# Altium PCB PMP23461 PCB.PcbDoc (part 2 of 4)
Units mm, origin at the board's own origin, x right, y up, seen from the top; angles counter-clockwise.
Board outline 240.04 x 159.92 mm, 6 copper layers (Layer 1, Layer 2, Layer 3, Layer 4, Layer 5, Layer 6), stack 2.017 mm thick; 241 components, 120 nets, 654 pads, 744 vias.
Unrouted connection lines stored in the file: 3.
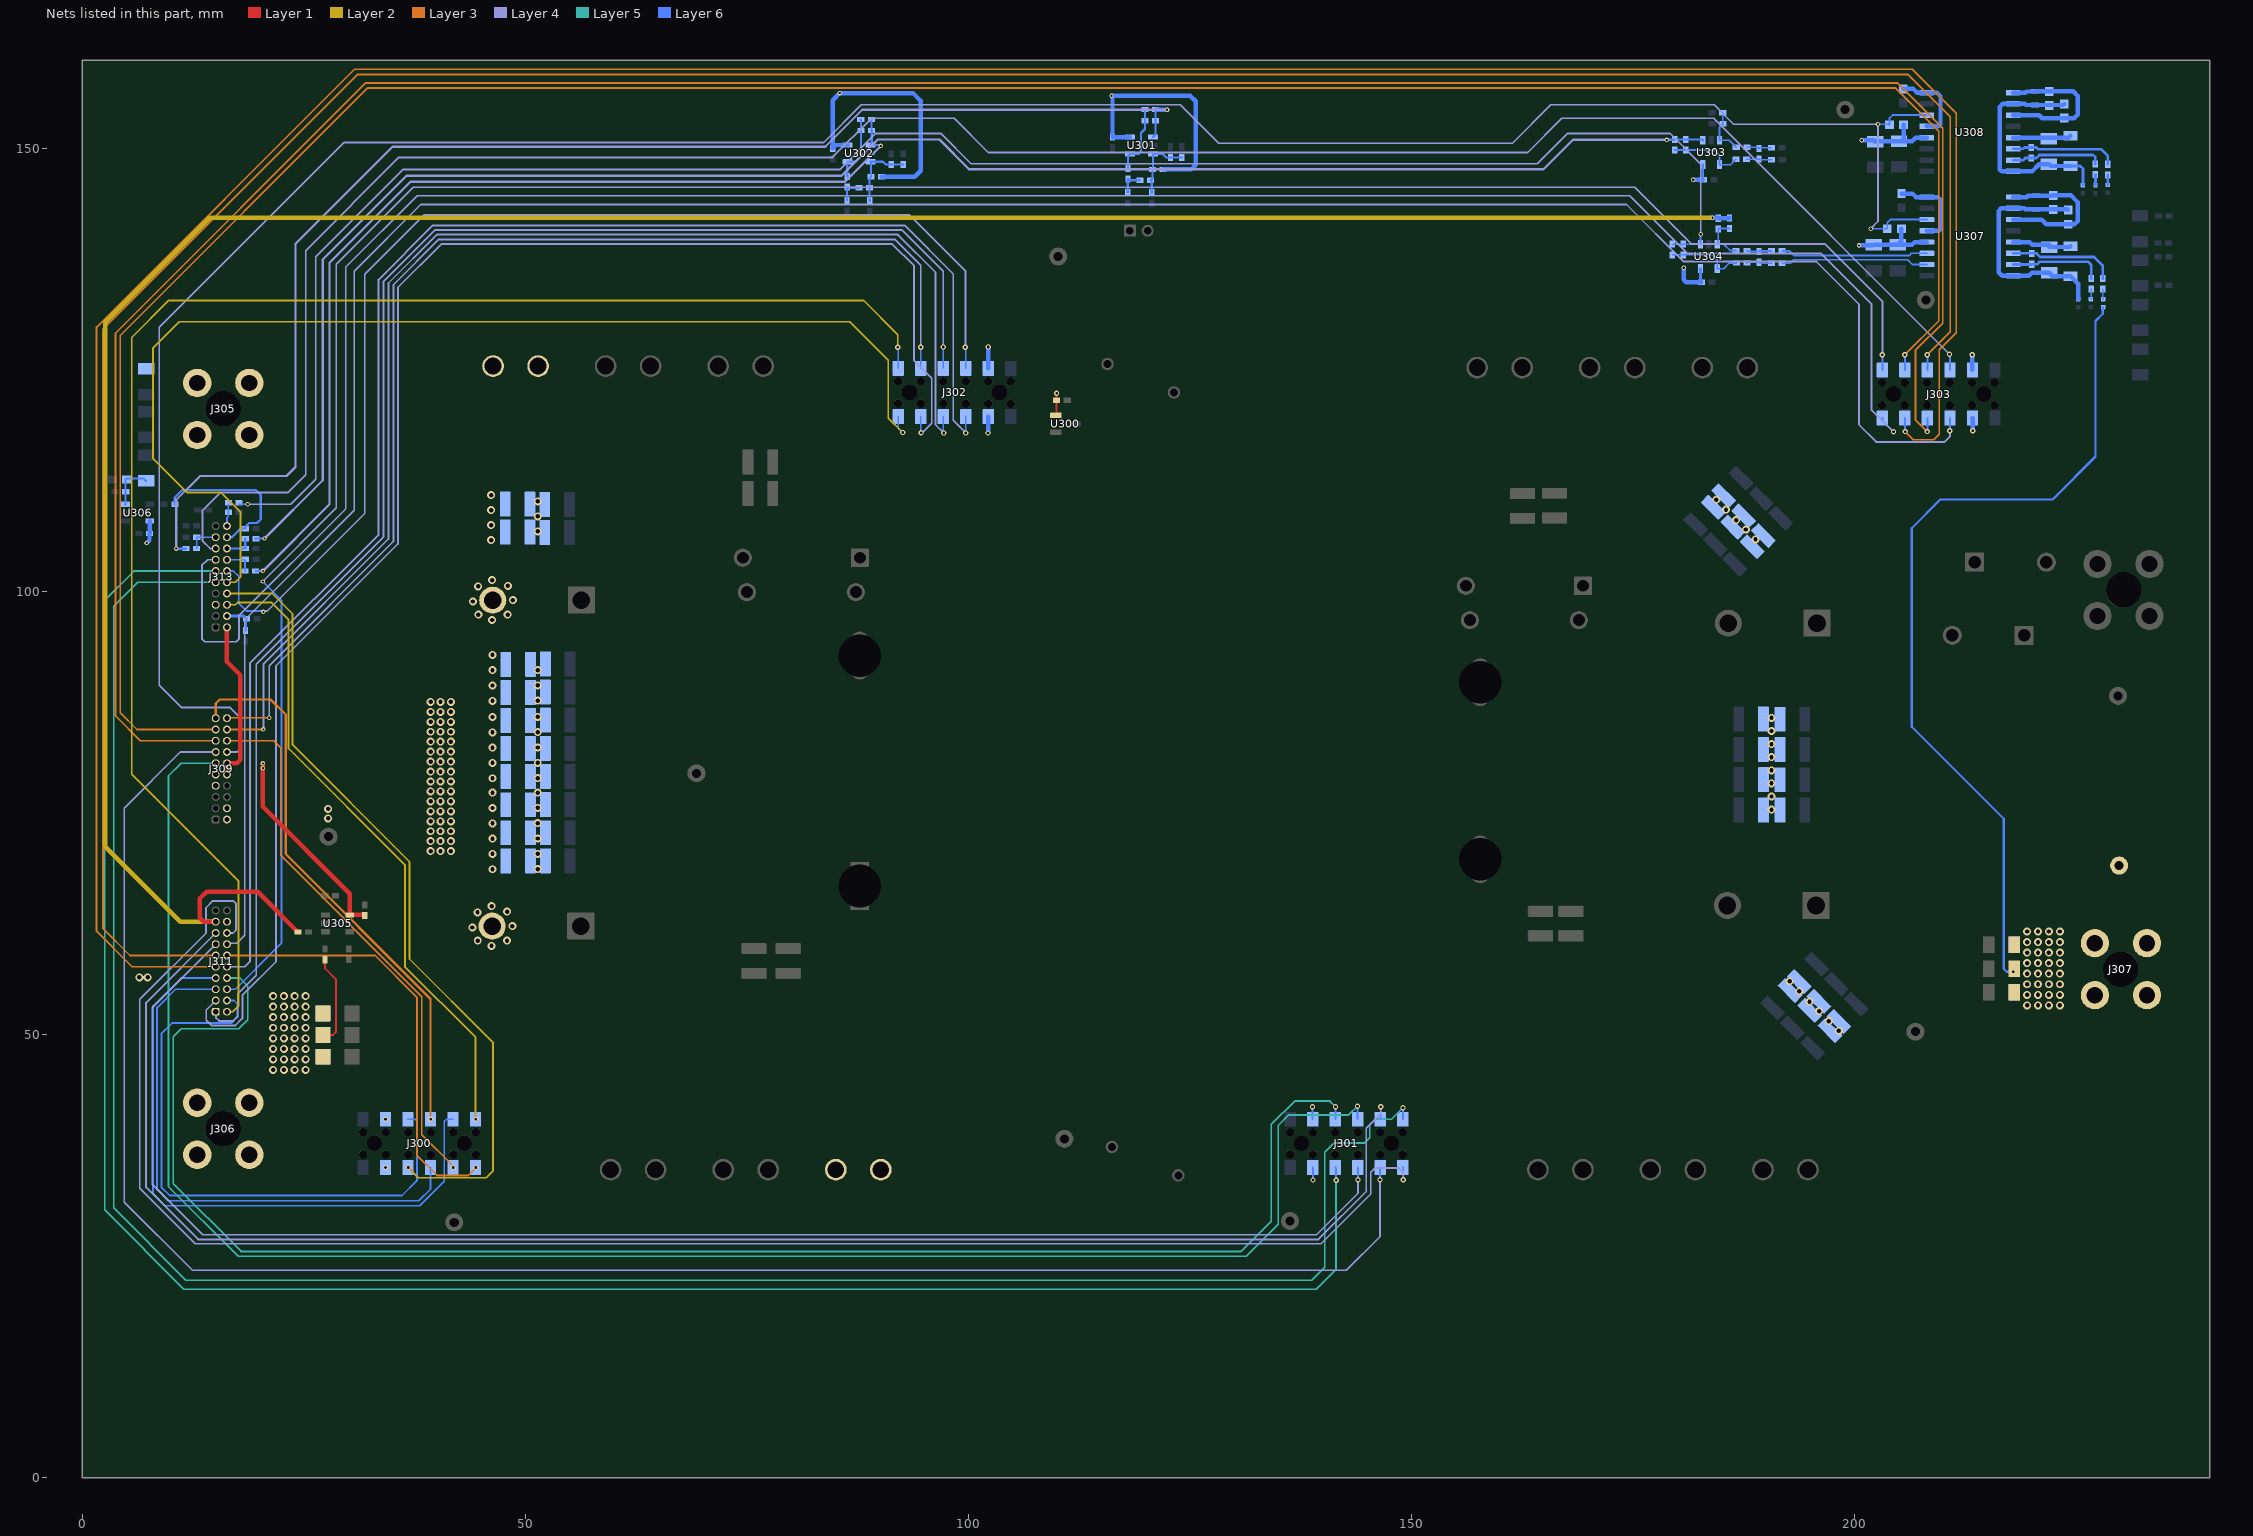
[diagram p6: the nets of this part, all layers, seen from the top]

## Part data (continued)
C319 C320: library part CMP-0090234-1, "470µF 500V Aluminum Electrolytic Capacitors Radial, Can - Snap-In 532.2mOhm @ 100Hz 15000 Hrs @ 85°C", Digikey Part Number=399-17944-ND, Leakage Current=6uA, Manufacturer=Kemet, Mouser Part Number=80-ALA7DA471DE500, Operating Temperature Range="-40°C to +85°C", Tolerance_%=20%, ValueDisplayed=470uF
C321 C360: library part CMP-0008647-2, "CAP, CERM, 0.1 uF, 50 V, +/- 5%, C0G/NP0, 1206_190", Cap_Case=1206, Manufacturer=TDK, Supplier Part Number 1=445-14655-1-ND, TempCo=C0G/NP0, Tolerance_%=5%, Value1=Unknown, Value2=50V, ValueDisplayed=0.1uF
C322 C330 C335 C338 C339 C348 C349 C350: library part CMP-0080610-1, "CAP, CERM, 0.1 µF, 25 V,+/- 10%, X7R, AEC-Q200 Grade 1, 0402", Cap_Case=0402, Manufacturer=TDK, Supplier Part Number 1=445-6902-1-ND, TempCo=X7R, Tolerance_%=10%, Value2=25V, ValueDisplayed=0.1µF
C323 C325: library part CMP-0090464-1, "300µF 500V Aluminum Electrolytic Capacitors Radial, Can - Snap-In 687.4mOhm @ 100Hz 7000 Hrs @ 105°C", Digikey Part Number=399-17946-ND, Leakage Current=450uA, Manufacturer=Kemet, Mouser Part Number=80-ALA8DA301CF500, Operating Temperature Range="-40°C to +105°C", Tolerance_%=20%, ValueDisplayed=300uF
C327: library part CMP-0080610-1, "CAP, CERM, 0.1 µF, 25 V,+/- 10%, X7R, AEC-Q200 Grade 1, 0402", Cap_Case=0402, Manufacturer=TDK, PartNumber=CGA2B3X7R1E104K050BB, Supplier Part Number 1=445-6902-1-ND, TempCo=X7R, Tolerance_%=10%, Value2=25V, ValueDisplayed=0.1µF
C329: library part CMP-0006317-2, "CAP, CERM, 2200 pF, 50 V, +/- 10%, X7R, AEC-Q200 Grade 1, 0402", Cap_Case=0402, Manufacturer=TDK, PartNumber=CGA2B2X7R1H222K050BA, Supplier Part Number 1=445-5606-1-ND, TempCo=X7R, Tolerance_%=10%, Value1="1.07794 ohm", Value2=50V, ValueDisplayed=2200pF
C332 C342: library part CMP-0006328-2, "CAP, CERM, 0.022 uF, 50 V, +/- 10%, X7R, AEC-Q200 Grade 1, 0402", Cap_Case=0402, Manufacturer=TDK, Supplier Part Number 1=445-6895-1-ND, TempCo=X7R, Tolerance_%=10%, Value1="0.141987 ohm", Value2=50V, ValueDisplayed=0.022uF
C334 C336 C341 C343 C347 C351: library part CMP-0006324-2, "CAP, CERM, 0.01 uF, 50 V, +/- 10%, X7R, AEC-Q200 Grade 1, 0402", Cap_Case=0402, Manufacturer=TDK, Supplier Part Number 1=445-6893-1-ND, TempCo=X7R, Tolerance_%=10%, Value1="0.333065 ohm", Value2=50V, ValueDisplayed=0.01uF
C337: library part CMP-0006317-2, "CAP, CERM, 2200 pF, 50 V, +/- 10%, X7R, AEC-Q200 Grade 1, 0402", Cap_Case=0402, Manufacturer=TDK, Supplier Part Number 1=445-5606-1-ND, TempCo=X7R, Tolerance_%=10%, Value1="1.07794 ohm", Value2=50V, ValueDisplayed=2200pF
C344 C346: library part CMP-0080702-1, "CAP, CERM, 0.1 µF, 16 V,+/- 5%, X7R, AEC-Q200 Grade 1, 0402", Cap_Case=0402, Manufacturer=MuRata, Supplier Part Number 1=490-16433-1-ND, TempCo=X7R, Tolerance_%=5%, Value2=16V, ValueDisplayed=0.1µF
C345: library part CMP-0006360-2, "CAP, CERM, 470 pF, 50 V, +/- 10%, X7R, AEC-Q200 Grade 1, 0402", Cap_Case=0402, Manufacturer=MuRata, Supplier Part Number 1=490-4913-1-ND, TempCo=X7R, Tolerance_%=10%, Value1=Unknown, Value2=50V, ValueDisplayed=470pF
C352 C354 C361 C363: library part CMP-0008530-2, "CAP, CERM, 1000 pF, 50 V, +/- 10%, X7R, 1206", Cap_Case=1206, Manufacturer=AVX, Supplier Part Number 1=478-1530-1-ND, TempCo=X7R, Tolerance_%=10%, Value1="0.427 ohm", Value2=50V, ValueDisplayed=1000pF
C353: library part CMP-0006325-2, "CAP, CERM, 0.1 uF, 50 V, +/- 10%, X7R, AEC-Q200 Grade 1, 0402", Cap_Case=0402, Manufacturer=TDK, Supplier Part Number 1=445-6899-1-ND, TempCo=X7R, Tolerance_%=10%, Value1="0.039064 ohm", Value2=50V, ValueDisplayed=0.1uF
C355 C364: library part CMP-0008509-2, "CAP, CERM, 1 uF, 25 V, +/- 10%, X7R, 1206", Cap_Case=1206, Manufacturer=AVX, Supplier Part Number 1=478-1567-1-ND, TempCo=X7R, Tolerance_%=10%, Value1="0.013 ohm", Value2=25V, ValueDisplayed=1uF
C356 C357 C365 C366: library part CMP-0079602-1, "CAP, CERM, 0.1 µF, 50 V,+/- 10%, X7R, AEC-Q200 Grade 1, 0603", Cap_Case=0603, Manufacturer=Kemet, Supplier Part Number 1=399-6856-1-ND, TempCo=X7R, Tolerance_%=10%, Value2=50V, ValueDisplayed=0.1µF
C358 C367: library part CMP-0076705-3, "CAP, CERM, 1 µF, 25 V,+/- 10%, X7R, AEC-Q200 Grade 1, 0603", Cap_Case=1.6x0.8x0.8mm, Manufacturer=TDK, Supplier Part Number 1=445-6931-1-ND, TempCo=X7R, Tolerance_%=10%, Value2=25V, ValueDisplayed=1µF
C359 C368: library part CMP-0006847-4, "CAP, CERM, 1000 pF, 50 V, +/- 10%, X7R, 0603", Cap_Case=0603, Manufacturer=Kemet, Supplier Part Number 1=399-1082-1-ND, TempCo=X7R, Tolerance_%=10%, Value1=Unknown, Value2=50V, ValueDisplayed=1000pF
C362: library part CMP-0006314-2, "CAP, CERM, 1000 pF, 50 V, +/- 10%, X7R, AEC-Q200 Grade 1, 0402", Cap_Case=0402, Manufacturer=TDK, Supplier Part Number 1=445-5605-1-ND, TempCo=X7R, Tolerance_%=10%, Value1="2.25564 ohm", Value2=50V, ValueDisplayed=1000pF
F300 F301: library part CMP-4956-0000-1, "25A AC 450V DC Fuse Cartridge, Ceramic Through Hole 3AB, 3AG, 1/4\" x 1-1/4\" (Axial)", Digikey Part Number=F10249-ND, Fuse Current=25A, Fuse Interrupt Dc Current=10000A, Manufacturer=Littelfuse, Mouser Part Number=576-0525025.MXEP, Operating Temperature Range="-55°C to +125°C"
FB300 FB301 FB302 FB303 FB304 FB305: library part CMP-0090600-1, "1.8 kOhms @ 100MHz 1 Signal Line Ferrite Bead 0402 (1005 Metric) 150mA 850mOhm", Digikey Part Number=445-172716-1-ND, Impedance At Frequency="1800O @ 100MHz", Manufacturer=TDK, Mouser Part Number=810-MMZ1005Y182CTD25, Operating Temperature Range="-55°C to +125°C", Test Frequency=100MHz, Tolerance_%=25%
J300 J301 J302 J303: library part CMP-0089984-1, "12 Position Receptacle, Bottom Entry Connector  Surface Mount", Current_A=4.1A, Digikey Part Number=HLE-106-02-G-DV-BE-A-ND, Manufacturer=Samtec, Mouser Part Number=200-HLE10602GDVBEA, Operating Temperature Range="-55°C to +125°C", Voltage_V=400V
J304: library part CMP-0090793-1, "Connector Header Through Hole 2 position 0.079\" (2.00mm)", Current_A=4A, Digikey Part Number=A98588-ND, Manufacturer="TE Connectivity", Mouser Part Number=571-2921612, Operating Temperature Range="-40°C to +221°C", Voltage_V=125V
J305 J306 J307 J308: library part CMP-0086784-1, "4 Pin Screw Terminal, Power Tap M4 Through Hole", Manufacturer="Würth Elektronik"
J309 J311 J313: library part CMP-0750171-1, "Receptacle, 1.27mm, 10x2, Gold, TH", Color=Black, Current_A=1A, Manufacturer="Sullins Connector Solutions"
LOGO300 LOGO301: library part CMP-0074835-1, "IEC 61010-1 High Voltage Warning"
LOGO302 LOGO303: library part CMP-0074837-1, "IEC 61010-1 Hot Surface Warning"
R300 R302 R304 R306 R309: library part CMP-0086941-2, "10 mOhms ±1% 1W Chip Resistor 1206 (3216 Metric) Automotive AEC-Q200, Current Sense, Moisture Resistant Metal Element", Manufacturer=Bourns, Power_W=1W, TempCo=50ppm/°C, Tolerance_%=1%, ValueDisplayed=10m
R301 R303 R305 R308 R310: library part CMP-0018567-2, "RES, 0.006, 1%, 0.5 W, 1206", Manufacturer=Vishay-Dale, Power_W=500mW, Supplier Part Number 1=WSLD-.006CT-ND, TempCo="110 ppm/C", Tolerance_%=1%, Value2=0.5W, Value_Code=6L000, ValueDisplayed=0.006
R307 R313 R324: library part CMP-0026454-2, "RES, 56.2, 1%, 0.063 W, AEC-Q200 Grade 0, 0402", Manufacturer=Vishay-Dale, Power_W=63mW, Supplier Part Number 1=541-56.2LCT-ND, TempCo="100 ppm/C", Tolerance_%=1%, Value2=0.063W, Value_Code=56R2, ValueDisplayed=56.2
R311 R316 R319 R329 R336 R348: library part CMP-0078779-1, "RES, 10.0 k, 1%, 0.2 W, AEC-Q200 Grade 0, 0402", Manufacturer=Panasonic, Power_W=200mW, Supplier Part Number 1=P17230CT-ND, TempCo="100 ppm/C", Tolerance_%=1%, Value2=0.2W, Value_Code=10k0, ValueDisplayed=10.0k
R312 R322 R332 R335 R340 R349 R360 R361: library part CMP-0026822-3, "RES, 0, 5%, 0.063 W, AEC-Q200 Grade 0, 0402", Manufacturer=Vishay-Dale, Power_W=63mW, Supplier Part Number 1=541-0.0JCT-ND, TempCo="200 ppm/C", Tolerance_%=5%, Value2=0.063W, Value_Code=0000, ValueDisplayed=0
R314 R315 R327 R328: library part CMP-0026071-3, "RES, 1.00 k, 1%, 0.063 W, AEC-Q200 Grade 0, 0402", Manufacturer=Vishay-Dale, Power_W=63mW, Supplier Part Number 1=541-1.00KLCT-ND, TempCo="100 ppm/C", Tolerance_%=1%, Value2=0.063W, Value_Code=1k00, ValueDisplayed=1.00k
R317: library part CMP-0026297-2, "RES, 332, 1%, 0.063 W, AEC-Q200 Grade 0, 0402", Manufacturer=Vishay-Dale, Power_W=63mW, Supplier Part Number 1=541-332LCT-ND, TempCo="100 ppm/C", Tolerance_%=1%, Value2=0.063W, Value_Code=332R, ValueDisplayed=332
R318 R331: library part CMP-0026590-2, "RES, 8.45 k, 1%, 0.063 W, AEC-Q200 Grade 0, 0402", Manufacturer=Vishay-Dale, Power_W=63mW, Supplier Part Number 1=541-8.45KLCT-ND, TempCo="100 ppm/C", Tolerance_%=1%, Value2=0.063W, Value_Code=8k45, ValueDisplayed=8.45k
R320 R321 R325 R326: library part CMP-0026238-2, "RES, 2.55 k, 1%, 0.063 W, AEC-Q200 Grade 0, 0402", Manufacturer=Vishay-Dale, Power_W=63mW, Supplier Part Number 1=541-2.55KLCT-ND, TempCo="100 ppm/C", Tolerance_%=1%, Value2=0.063W, Value_Code=2k55, ValueDisplayed=2.55k
R323 R341: library part CMP-0025979-3, "RES, 11.0, 1%, 0.063 W, AEC-Q200 Grade 0, 0402", Manufacturer=Vishay-Dale, Power_W=63mW, Supplier Part Number 1=541-11.0LCT-ND, TempCo="100 ppm/C", Tolerance_%=1%, Value2=0.063W, Value_Code=11R0, ValueDisplayed=11.0
R330: library part CMP-0026337-2, "RES, 3.65 k, 1%, 0.063 W, AEC-Q200 Grade 0, 0402", Manufacturer=Vishay-Dale, Power_W=63mW, Supplier Part Number 1=541-3.65KLCT-ND, TempCo="100 ppm/C", Tolerance_%=1%, Value2=0.063W, Value_Code=3k65, ValueDisplayed=3.65k
R333: library part CMP-0017331-3, "RES, 12.4 k, 1%, 0.25 W, AEC-Q200 Grade 0, 1206", Manufacturer=Panasonic, Power_W=250mW, Supplier Part Number 1=P12.4KFCT-ND, TempCo="100 ppm/C", Tolerance_%=1%, Value2=0.25W, Value_Code=12k4, ValueDisplayed=12.4k
R334 R354: library part CMP-0026553-2, "RES, 7.15 k, 1%, 0.063 W, AEC-Q200 Grade 0, 0402", Manufacturer=Vishay-Dale, Power_W=63mW, Supplier Part Number 1=541-7.15KLCT-ND, TempCo="100 ppm/C", Tolerance_%=1%, Value2=0.063W, Value_Code=7k15, ValueDisplayed=7.15k
R337 R338 R343 R344: library part CMP-0026938-5, "RES, 4.7 k, 5%, 0.063 W, AEC-Q200 Grade 0, 0402", Manufacturer=Vishay-Dale, Power_W=63mW, Supplier Part Number 1=541-4.7KJCT-ND, TempCo="200 ppm/C", Tolerance_%=5%, Value2=0.063W, Value_Code=4k70, ValueDisplayed=4.7k
R339: library part CMP-0022599-4, "RES, 7.15 k, 1%, 0.1 W, AEC-Q200 Grade 0, 0603", Manufacturer=Vishay-Dale, Power_W=100mW, Supplier Part Number 1=541-7.15KHCT-ND, TempCo="100 ppm/C", Tolerance_%=1%, Value2=0.1W, Value_Code=7k15, ValueDisplayed=7.15k
R342 R356: library part CMP-0026021-3, "RES, 150 k, 1%, 0.063 W, AEC-Q200 Grade 0, 0402", Manufacturer=Vishay-Dale, Power_W=63mW, Supplier Part Number 1=541-150KLCT-ND, TempCo="100 ppm/C", Tolerance_%=1%, Value2=0.063W, Value_Code=150k
R345 R351 R353: library part CMP-0016861-3, "RES, 2.00 M, 1%, 0.25 W, AEC-Q200 Grade 0, 1206", Manufacturer=Vishay-Dale, Power_W=250mW, Supplier Part Number 1=541-2.00MFCT-ND, TempCo="100 ppm/C", Tolerance_%=1%, Value2=0.25W, Value_Code=2M00, ValueDisplayed=2.00M
R346 R347: library part CMP-0026070-3, "RES, 19.6, 1%, 0.063 W, AEC-Q200 Grade 0, 0402", Manufacturer=Vishay-Dale, Power_W=63mW, Supplier Part Number 1=541-19.6LCT-ND, TempCo="100 ppm/C", Tolerance_%=1%, Value2=0.063W, Value_Code=19R6, ValueDisplayed=19.6
R350 R352 R355: library part CMP-0016927-3, "RES, 365 k, 1%, 0.25 W, AEC-Q200 Grade 0, 1206", Manufacturer=Vishay-Dale, Power_W=250mW, Supplier Part Number 1=541-365KFCT-ND, TempCo="100 ppm/C", Tolerance_%=1%, Value2=0.25W, Value_Code=365k
R357 R358: library part CMP-0026328-2, "RES, 39.2, 1%, 0.063 W, AEC-Q200 Grade 0, 0402", Manufacturer=Vishay-Dale, Power_W=63mW, Supplier Part Number 1=541-39.2LCT-ND, TempCo="100 ppm/C", Tolerance_%=1%, Value2=0.063W, Value_Code=39R2, ValueDisplayed=39.2
R359 R362: library part CMP-0025814-4, "RES, 47 k, 5%, 0.1 W, AEC-Q200 Grade 0, 0603", Manufacturer=Vishay-Dale, Power_W=100mW, Supplier Part Number 1=541-47KGCT-ND, TempCo="200 ppm/C", Tolerance_%=5%, Value2=0.1W, Value_Code=47k0, ValueDisplayed=47k
T300: library part CMP-0090959-1, "PRIMARY SIDE ROGOWSKI (PMP22495)", Manufacturer="Renco Electronics", Operating Temperature Range=to
T301: library part CMP-0090960-2, "Secondary Side Rogowski (PMP22495)", Manufacturer="Renco Electronics", Operating Temperature Range=to
T302: library part CMP-0090781-3, "TRANSFORMER", Manufacturer=Cyntec, Operating Temperature Range=to, Voltage_Isolation_Vrms=2000VDC
TP300 TP301 TP302 TP303 TP304 TP305 TP306 TP307 TP308 TP309 TP310 TP311 TP312 TP313 TP314 TP315 TP316 TP317 TP318 TP319 TP320 TP321 TP322 TP323: library part CMP-0055026-1, Manufacturer=Mill-Max, Supplier Part Number 1=0312-015153427100-ND
TP324 TP325: library part CMP-0055138-1, "Test Point, Miniature, Black, TH", Color=Black, Manufacturer=Keystone, Supplier Part Number 1=36-5001-ND
TP326: library part CMP-0055137-1, "Test Point, Miniature, Red, TH", Color=Red, Manufacturer=Keystone, Supplier Part Number 1=36-5000-ND
TP327 TP328 TP329 TP330 TP331 TP332 TP333 TP334: library part CMP-0055138-2, "Test Point, Miniature, Black, TH", Color=Black, Manufacturer="Keystone Electronics", Supplier Part Number 1=36-5001-ND
U300: library part CMP-0090472-1, "Temperature Sensor Analog, Local -40°C ~ 150°C 10mV/°C SOT-23-3", Digikey Part Number=296-TMP235AEDBZRQ1CT-ND, Manufacturer="Texas Instruments", Max Supply Voltage=5.5V, Min Supply Voltage=2.3V, Mouser Part Number=595-TMP235AEDBZRQ1, Operating Supply Current=9uA, Operating Temperature Range="-40°C to +150°C", Output Voltage=500mV
U301: library part CMP-0032028-2, "CMOS Amplifier 1 Circuit Rail-to-Rail SOT-23-5", Digikey Part Number=296-TLV365DBVRCT-ND, Input Bias Current=0.000005uA, Input Offset Voltage=0.4mV, Manufacturer="Texas Instruments", Max Supply Voltage=5.5V, Min Supply Voltage=2.2V, Mouser Part Number=595-TLV365DBVR, Nominal Supply Current=4.6mA, Operating Temperature Range="-40°C to +125°C", Output Current Per Channel=85mA, Voltage Gain=120dB
U302: library part CMP-0032028-2, "CMOS Amplifier 1 Circuit Rail-to-Rail SOT-23-5", Digikey Part Number=296-TLV365DBVRQ1-ND, Input Bias Current=0.000005uA, Input Offset Voltage=0.4mV, Manufacturer="Texas Instruments", Max Supply Voltage=5.5V, Min Supply Voltage=2.2V, Mouser Part Number=595-TLV365DBVRQ1, Nominal Supply Current=4.6mA, Operating Temperature Range="-40°C to +125°C", Output Current Per Channel=85mA, Voltage Gain=120dB
U303 U304 U306: library part CMP-0077859-1, "Automotive Qualified Precision, Zero-Crossover, 20MHz, 0.9pA Ib, RRIO, CMOS Operational Amplifier, DBV0005A (SOT-23-5)", Alternate Manufacturer="Texas Instruments", Alternate PartNumber=OPA320AQDBVTQ1
U305: library part CMP-0068826-2, "17 MHz, Low Noise, CMOS Input, 1.8V Operational Amplifiers, DBV0005A (SOT-23-5)", Manufacturer="Texas Instruments", Operating Temperature Range="-40 to 125 C", Rating=Automotive
U307: library part CMP-0090884-2, "±50-mV input, precision reinforced isolated amplifier with integrated DC/DC converter 16-SOIC -40 to 125", Input Bias Current=-36uA, Input Offset Voltage=0.1mV, Manufacturer="Texas Instruments", Max Supply Voltage=5.5V, Min Supply Voltage=3V, Nominal Supply Current=27.5-29.5mA, Operating Temperature Range="-40°C to +125°C", Output Current Per Channel=14mA
U308: library part CMP-0090627-1, "Precision, ±1-V Input, Reinforced Isolated Amplifier With Integrated DC/DC Converter", Input Bias Current=0.01uA, Manufacturer="Texas Instruments", Max Supply Voltage=5.5V, Min Supply Voltage=3V, Nominal Supply Current=27.5-28.5mA, Operating Temperature Range="-40°C to +125°C"

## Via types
v1: diameter 0.9, hole 0.5, Layer 1 to Layer 6, 634 vias
v2: diameter 0.6, hole 0.3, Layer 1 to Layer 6, 52 vias
v3: diameter 0.5, hole 0.25, Layer 1 to Layer 6, 42 vias
v4: diameter 4, hole 4, Layer 1 to Layer 6, 12 vias
v5: diameter 3, hole 2.2, Layer 1 to Layer 6, 4 vias

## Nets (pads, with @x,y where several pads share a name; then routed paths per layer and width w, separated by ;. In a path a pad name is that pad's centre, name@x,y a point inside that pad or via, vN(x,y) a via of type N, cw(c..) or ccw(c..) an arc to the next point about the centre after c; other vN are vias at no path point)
1V65_REF: C343.1 J311.17 R334.1 R342.1 | length 280.8
  Layer 1 w0.508: J311.17@15.042,62.725 13.702,62.725 13.258,63.169 13.258,65.354 14.02,66.116 19.77,66.116 R342.1@24.316,61.57
  Layer 2 w0.508: J311.17@15.042,62.725 11.032,62.725 2.59,71.168 2.59,130.378 14.375,142.164 177.977,142.164 v3(183.932,142.173)
  Layer 6 w0.508: v3(183.932,142.173) 184.542,142.173 C343.1@184.604,142.11 185.849,142.11 R334.1@185.874,142.135
3V3_PRI: C330.1 C338.1 C339.1 C348.1 C349.1 C350.1 C354.1 C355.1 C363.1 C364.1 J309.10 J309.12 J313.2 R316.2 R329.2 R359.1 R362.1 U301.5 U302.5 U303.5 U304.5 U305.5 U306.5 U307.12 U308.12 | length 129.1
  Layer 1 w0.5: J309.10@16.312,79.337 J309.12@16.312,80.607 17.439,80.607 17.831,80.998 17.831,90.551 16.312,92.07 J313.2@16.312,95.948 ; v3(20.37,80.594) 20.37,75.692 30.168,65.894 U305.5@30.168,63.49 31.635,63.49 C349.1@31.815,63.31
  Layer 6 w0.305: U304.5@182.588,136.417 182.588,135.01 C348.1@182.701,134.896 ; C339.1@182.844,146.511 U303.5@182.844,148.155
  Layer 6 w0.5: v3(7.264,105.461) 7.568,105.764 C350.1@7.568,106.528 7.598,106.558 U306.5@7.598,107.94 ; U302.5@86.345,150.371 85.04,150.371 C338.1@84.668,150 84.668,155.433 v3(85.47,156.235) 93.725,156.235 94.614,155.346 94.614,147.472 93.921,146.78 R329.2@90.2,146.78 ; U301.5@118.217,151.267 C330.1@116.236,151.267 116.236,155.823 v3(116.128,155.931) 124.992,155.931 125.627,155.296 125.627,148.133 125.109,147.614 R316.2@121.946,147.614 ; v3(180.695,136.53) 180.695,135.179 180.977,134.896 C348.1@182.701,134.896 ; v3(181.784,146.457) 182.789,146.457 C339.1@182.844,146.511 ; v3(200.481,139.04) 202.098,139.04 C354.1@202.148,139.09 202.162,139.104 C355.1@204.864,139.104 ; v3(200.785,150.905) 202.144,150.905 C363.1@202.3,150.748 202.352,150.8 C364.1@204.991,150.8 C364.1@205.348,150.8 ; R359.1@205.259,140.916 205.259,139.499 C355.1@204.864,139.104 ; R362.1@205.513,152.651 205.513,150.965 C364.1@205.348,150.8 ; U308.12@208.119,151.203 206.872,151.203 206.469,150.8 C364.1@205.348,150.8 ; U307.12@208.144,139.418 206.771,139.418 206.457,139.104 C355.1@204.864,139.104
  other v3: 20.37,80.035
3V3_REF: J311.18
5V_PRI: C322.1 J300.10 J301.10 J302.10 J303.10 J309.7 J309.9 J313.5 U300.1 | length 8.1
  Layer 1 w0.2: C322.1@109.93,121.578 v2(109.93,122.343)
  Layer 1 w0.254: U300.1@109.853,119.861 109.93,119.939 C322.1@109.93,121.578
  Layer 6 w0.203: J301.10@138.833,34.996 138.861,34.968 v2(138.861,33.579)
  Layer 6 w0.5: J302.10@102.224,125.17 102.224,127.574 v2(102.234,127.584) ; J303.10@213.273,124.993 v2(213.273,126.705)
  other v2: 34.211,34.996
12V_PRI: J300.9 J301.9 J302.9 J303.9 J309.2 J309.4 | length 4.8
  Layer 6 w0.203: v2(138.81,41.859) 138.81,40.459 J301.9@138.833,40.436
  Layer 6 w0.5: v2(102.183,117.881) 102.224,117.922 J302.9@102.224,119.73 ; J303.9@213.273,119.553 213.308,119.517 v2(213.308,118.11)
  other v1: 6.426,56.439 7.366,56.439 27.737,74.397 27.737,75.463
  other v2: 34.211,40.436
BATT_RTN: FB302.1 J307.1 R301.2 R303.2 R305.2 R308.2 R310.2 TP325.1 | length 96.6
  Layer 6 w0.254: v2(217.9,57.068) 217.144,57.068 216.81,57.401 216.81,74.341 206.423,84.729 206.423,107.134 209.652,110.363 222.326,110.363 227.177,115.213 227.177,130.515 227.98,131.318 227.98,132.034 FB302.1@228.03,132.084
  other v1: 219.455,53.289 220.674,53.289 221.893,53.289 223.138,53.289 219.455,54.479 220.674,54.479 221.893,54.479 223.138,54.479 219.455,55.67 220.674,55.67 221.893,55.67 223.138,55.67 219.455,56.86 220.674,56.86 221.893,56.86 223.138,56.86 219.455,58.05 220.674,58.05 221.893,58.05 223.138,58.05 219.455,59.24 220.674,59.24 221.893,59.24 223.138,59.24 219.455,60.43 220.674,60.43 221.893,60.43 223.138,60.43 219.455,61.62 220.674,61.62 221.893,61.62 223.138,61.62
CLLLC_GAN_OC_PRIM_LEG1_H: J302.4 J309.20 | length 134
  Layer 3 w0.203: J309.20@16.312,85.687 16.376,85.75 v3(21.083,85.75)
  Layer 4 w0.203: v3(21.083,85.75) 21.083,91.619 35.102,105.639 35.102,134.595 40.233,139.725 91.663,139.725 94.604,136.784 v2(94.604,127.559)
  Layer 6 w0.203: J309.20@16.312,85.687 J309.20@16.376,85.75 ; J302.4@94.604,125.17 v2(94.604,127.559)
CLLLC_GAN_OC_PRIM_LEG1_L: J302.5 J309.18 | length 146.5
  Layer 3 w0.203: J309.18@16.312,84.417 16.325,84.43 v3(20.421,84.43)
  Layer 4 w0.203: v3(20.421,84.43) 20.421,91.796 34.543,105.918 34.543,134.798 40.004,140.259 92.023,140.259 96.265,136.017 96.265,118.821 v2(97.205,117.881)
  Layer 6 w0.203: J302.5@97.144,119.73 97.144,117.942 v2(97.205,117.881)
CLLLC_GAN_OC_PRIM_LEG2_H: J300.4 J309.16 | length 61.8
  Layer 3 w0.203: J309.16@16.312,83.147 21.577,83.147 22.377,82.347 22.377,70.206 38.303,54.28 38.303,38.684 41.831,35.157 v2(41.831,34.996)
CLLLC_GAN_OC_PRIM_LEG2_L: J300.5 J309.19 | length 62.9
  Layer 3 w0.254: J309.19@15.042,85.687 15.042,87.356 15.494,87.808 21.234,87.808 22.936,86.106 22.936,70.358 39.291,54.004 v2(39.291,40.436)
CLLLC_GAN_OC_SEC_LEG1_H: J303.4 J309.17 | length 301.4
  Layer 3 w0.203: J309.17@15.042,84.417 6.159,84.417 4.266,86.309 4.266,128.88 32.206,156.82 204.572,156.82 209.468,151.923 209.468,130.511 v2(205.653,126.695)
  Layer 6 w0.203: J303.4@205.653,124.993 v2(205.653,126.695)
CLLLC_GAN_OC_SEC_LEG1_L: J303.5 J309.15 | length 313.2
  Layer 3 w0.203: J309.15@15.042,83.147 6.54,83.147 3.733,85.954 3.733,129.134 31.978,157.378 204.8,157.378 209.93,152.248 209.93,130.277 206.847,127.193 206.847,119.364 v2(208.177,118.034)
  Layer 6 w0.203: v2(208.177,118.034) 208.193,118.049 J303.5@208.193,119.553
CLLLC_GAN_OC_SEC_LEG2_H: J301.4 J309.13 | length 211.7
  Layer 4 w0.203: J309.13@15.042,81.877 11.062,81.877 4.723,75.538 4.723,31.09 12.42,23.393 142.62,23.393 146.43,27.203 v2(146.43,33.604)
  Layer 6 w0.203: v2(146.43,33.604) 146.43,34.973 J301.4@146.453,34.996
CLLLC_GAN_OC_SEC_LEG2_L: J301.5 J309.11 | length 204.7
  Layer 5 w0.203: J309.11@15.042,80.607 11.137,80.607 9.702,79.172 9.702,32.842 17.576,24.968 131.342,24.968 134.949,28.575 134.949,39.726 136.143,40.919 142.899,40.919 v2(143.89,41.91)
  Layer 6 w0.203: v2(143.89,41.91) 143.89,40.459 J301.5@143.913,40.436
CLLLC_IPRIM: C344.1 J313.4 R346.2 | length 3.7
  Layer 6 w0.305: J313.4@16.312,97.218 18.224,97.218 C344.1@18.516,96.926 18.414,96.825 R346.2@18.414,95.58
CLLLC_IPRIM_TANK: C333.1 J313.14 R324.2 | length 3.3
  Layer 6 w0.203: J313.14@16.312,103.568 18.284,103.568 18.347,103.505 R324.2@18.347,102.311
CLLLC_ISEC: C342.1 J313.20 R341.2 | length 2.5
  Layer 6 w0.203: J313.20@16.312,107.378 16.312,108.307 16.468,108.463 C342.1@16.468,108.949 R341.2@16.468,109.83
CLLLC_ISEC_TANK: C328.1 J313.17 R313.2 | length 3.4
  Layer 6 w0.203: R313.2@12.893,104.838 12.902,104.848 C328.1@12.902,106.096 12.915,106.108 J313.17@15.042,106.108
CLLLC_PRIM_FAULT_LEG1_H: J302.6 J311.1 | length 171.7
  Layer 4 w0.203: J311.1@15.042,52.565 15.067,52.54 15.067,51.892 15.423,51.537 16.992,51.537 17.525,52.07 17.525,54.585 19.608,56.667 19.608,91.77 33.984,106.147 33.984,134.976 39.775,140.767 92.521,140.767 97.144,136.144 v2(97.144,127.584)
  Layer 6 w0.203: J302.6@97.144,125.17 v2(97.144,127.584)
CLLLC_PRIM_FAULT_LEG1_L: J302.3 J311.3 | length 180.4
  Layer 4 w0.203: J311.3@15.042,53.835 13.969,52.762 13.969,51.613 14.553,51.029 17.271,51.029 18.058,51.816 18.058,54.432 21.843,58.217 21.843,91.592 35.61,105.359 35.61,134.315 40.487,139.192 91.388,139.192 93.845,136.735 93.845,126.016 95.833,124.028 95.833,118.974 94.777,117.918 v2(94.639,117.918)
  Layer 6 w0.203: J302.3@94.604,119.73 94.604,117.953 v2(94.639,117.918)
CLLLC_PRIM_FAULT_LEG2_H: J300.6 J311.5 | length 62.4
  Layer 6 w0.203: J311.5@15.042,55.105 10.502,55.105 8.432,53.035 8.432,32.512 9.702,31.242 37.972,31.242 39.291,32.561 J300.6@39.291,34.996
CLLLC_PRIM_FAULT_LEG2_L: J300.3 J311.7 | length 72
  Layer 6 w0.203: J311.7@15.042,56.375 11.137,56.375 7.975,53.213 7.975,32.029 9.321,30.683 38.074,30.683 40.842,33.452 40.842,40.186 41.092,40.436 J300.3@41.831,40.436
CLLLC_PRIM_LEG1_H: J302.8 J313.12 | length 134.9
  Layer 4 w0.203: v3@20.395,97.79 20.852,97.79 31.852,108.789 31.852,135.788 38.532,142.469 93.342,142.469 99.641,136.169 v2(99.641,127.559)
  Layer 6 w0.203: J313.12@16.312,102.298 17.03,102.298 17.64,101.688 17.64,98.676 18.526,97.79 v3@20.395,97.79 ; v2(99.641,127.559) 99.684,127.516 J302.8@99.684,125.17
  other v3: 20.421,97.688
CLLLC_PRIM_LEG1_H_TEMP: J302.2 J311.2 | length 175.6
  Layer 2 w0.203: J311.2@16.312,52.565 16.968,52.565 17.602,53.2 17.602,67.334 5.563,79.374 5.563,128.651 9.754,132.842 88.138,132.842 91.998,128.982 v2(91.998,127.559)
  Layer 6 w0.203: v2(91.998,127.559) 92.064,127.492 J302.2@92.064,125.17
CLLLC_PRIM_LEG1_L: J302.1 J313.10 | length 130.8
  Layer 2 w0.203: J313.10@16.312,101.028 17.26,101.028 17.855,101.623 17.855,108.941 15.62,111.176 11.785,111.176 7.975,114.986 7.975,127.483 10.921,130.429 86.588,130.429 90.931,126.086 90.931,119.558 v2(92.557,117.932)
  Layer 6 w0.203: J302.1@92.064,119.73 92.064,118.425 v2(92.557,117.932)
CLLLC_PRIM_LEG1_L_TEMP: J302.7 J311.10 | length 175.8
  Layer 4 w0.203: J311.10@16.312,57.645 18.338,57.645 18.897,58.204 18.897,91.872 33.425,106.401 33.425,135.179 39.547,141.3 92.785,141.3 98.266,135.819 98.266,119.299 v2(99.684,117.881)
  Layer 6 w0.203: v2(99.684,117.881) J302.7@99.684,119.73
CLLLC_PRIM_LEG2_H: J300.8 J313.8 | length 91
  Layer 2 w0.203: J313.8@16.312,99.758 21.419,99.758 23.724,97.453 23.724,82.677 36.906,69.494 36.906,58.522 46.319,49.109 46.319,34.559 45.593,33.833 37.914,33.833 v2(36.751,34.996)
CLLLC_PRIM_LEG2_H_TEMP: J300.2 J311.12 | length 49.2
  Layer 3 w0.203: J311.12@16.312,58.915 33.033,58.915 37.744,54.204 37.744,36.363 40.02,34.087 43.536,34.087 44.371,34.922 v2(44.371,34.996)
CLLLC_PRIM_LEG2_L: J300.1 J313.6 | length 73
  Layer 2 w0.203: J313.6@16.312,98.488 17.259,98.488 17.501,98.73 21.349,98.73 23.265,96.813 23.265,82.272 36.39,69.147 36.39,57.663 44.371,49.682 v2(44.371,40.436)
CLLLC_PRIM_LEG2_L_TEMP: J300.7 J311.4 | length 67.2
  Layer 6 w0.203: J311.4@16.312,53.835 17.106,53.835 17.5,53.442 17.5,51.968 16.814,51.283 10.108,51.283 8.914,50.089 8.914,32.766 9.854,31.827 36.067,31.827 37.743,33.503 37.743,40.234 37.541,40.436 J300.7@36.751,40.436
CLLLC_SEC_FAULT_LEG1_H: J303.6 J311.11 | length 333.6
  Layer 3 w0.203: J311.11@15.042,58.915 5.371,58.915 2.336,61.951 2.336,129.616 31.063,158.344 205.969,158.344 210.774,153.538 210.774,129.286 v2(208.193,126.705)
  Layer 6 w0.203: J303.6@208.193,124.993 v2(208.193,126.705)
CLLLC_SEC_FAULT_LEG1_L: J303.3 J311.9 | length 350.3
  Layer 3 w0.203: J311.9@15.042,57.645 5.6,57.645 1.599,61.646 1.599,129.819 30.708,158.928 206.477,158.928 211.455,153.949 211.455,129.185 209.532,127.262 209.532,117.723 208.928,117.119 206.603,117.119 v2(205.688,118.034)
  Layer 6 w0.203: J303.3@205.653,119.553 205.653,118.069 v2(205.688,118.034)
CLLLC_SEC_FAULT_LEG2_H: J301.6 J311.13 | length 173.3
  Layer 4 w0.203: J311.13@15.042,60.185 7.873,53.016 7.873,33.096 13.563,27.407 139.256,27.407 143.941,32.092 v2(143.941,33.604)
  Layer 6 w0.203: J301.6@143.913,34.996 143.941,34.968 v2(143.941,33.604)
CLLLC_SEC_FAULT_LEG2_L: J301.3 J311.15 | length 186
  Layer 4 w0.203: J311.15@15.042,61.455 7.187,53.6 7.187,32.741 13.055,26.873 139.47,26.873 144.881,32.283 144.881,39.421 146.506,41.046 v2(146.506,41.834)
  Layer 6 w0.203: J301.3@146.453,40.436 146.506,40.489 v2(146.506,41.834)
CLLLC_SEC_LEG1_H: J303.8 J313.15 | length 251.6
  Layer 4 w0.203: J313.15@15.042,104.838 14.414,104.838 13.537,105.715 13.537,109.118 15.595,111.176 23.216,111.176 25.196,113.156 25.196,138.454 35.712,148.971 84.633,148.971 89.052,153.391 98.374,153.391 102.235,149.53 163.093,149.53 166.954,153.391 184.073,153.391 v2(210.692,126.771)
  Layer 6 w0.203: v2(210.692,126.771) 210.733,126.73 J303.8@210.733,124.993
CLLLC_SEC_LEG1_H_TEMP: J303.2 J311.6 | length 280.4
  Layer 4 w0.203: v3(20.344,101.117) 28.651,109.424 28.651,136.906 37.351,145.606 175.17,145.606 181.584,139.192 196.672,139.192 203.113,132.751 v2(203.113,126.721)
  Layer 6 w0.203: J311.6@16.312,55.105 17.271,55.105 22.46,60.294 22.46,99.002 v3(20.344,101.117) ; J303.2@203.113,124.993 v2(203.113,126.721)
CLLLC_SEC_LEG1_L: J303.1 J313.13 | length 259.6
  Layer 4 w0.203: J313.13@15.042,103.568 14.121,103.568 13.486,102.933 13.486,94.64 13.817,94.31 17.373,94.31 17.663,94.6 17.663,97.242 29.718,109.297 29.718,136.601 37.77,144.653 174.599,144.653 181.139,138.112 196.228,138.112 201.878,132.462 201.878,120.499 v2(204.368,118.008)
  Layer 6 w0.203: J303.1@203.113,119.553 203.113,119.264 v2(204.368,118.008)
CLLLC_SEC_LEG1_L_TEMP: J303.7 J311.14 | length 287.1
  Layer 4 w0.203: J311.14@16.312,60.185 16.426,60.3 17.398,60.3 18.312,61.214 18.312,96.774 30.683,109.145 30.683,136.144 38.202,143.662 174.243,143.662 180.695,137.211 195.682,137.211 200.481,132.411 200.481,118.796 202.413,116.864 210.132,116.864 210.733,117.465 v2(210.733,118.11)
  Layer 6 w0.203: v2(210.733,118.11) J303.7@210.733,119.553
CLLLC_SEC_LEG2_H: J301.8 J313.11 | length 237.8
  Layer 5 w0.203: J313.11@15.042,102.298 5.828,102.298 2.514,98.984 2.514,30.201 11.454,21.26 139.216,21.26 141.477,23.52 v2(141.477,33.559)
  Layer 6 w0.203: J301.8@141.373,34.996 141.477,34.892 v2(141.477,33.559)
CLLLC_SEC_LEG2_H_TEMP: J301.2 J311.16 | length 195.3
  Layer 4 w0.203: J311.16@16.312,61.455 17.004,61.455 17.347,61.798 17.347,64.77 17.042,65.075 14.731,65.075 13.944,64.287 13.944,61.443 6.476,53.975 6.476,32.639 12.737,26.378 139.766,26.378 145.389,32 145.389,34.468 145.846,34.925 148.564,34.925 149.046,34.442 v2(149.046,33.604)
  Layer 6 w0.203: J301.2@148.993,34.996 149.046,34.943 v2(149.046,33.604)
CLLLC_SEC_LEG2_L: J301.1 J313.9 | length 247.2
  Layer 5 w0.203: J313.9@15.042,101.028 6.247,101.028 3.53,98.311 3.53,30.429 11.683,22.276 138.708,22.276 140.182,23.749 140.182,36.703 141.248,37.77 144.703,37.77 145.262,38.329 145.262,39.802 145.896,40.436 147.725,40.436 v2(149.021,41.732)
  Layer 6 w0.203: J301.1@148.993,40.436 149.021,40.464 v2(149.021,41.732)
CLLLC_SEC_LEG2_L_TEMP: J301.7 J311.8 | length 181.7
  Layer 5 w0.203: J311.8@16.312,56.375 17.767,56.375 18.668,55.475 18.668,51.659 17.657,50.648 11.15,50.648 10.261,49.759 10.261,33.172 17.906,25.527 130.758,25.527 134.162,28.931 134.162,39.853 136.795,42.486 140.766,42.486 v2(141.401,41.852)
  Layer 6 w0.203: J301.7@141.373,40.436 141.401,40.464 v2(141.401,41.852)
CLLLC_SEC_SIDE_SENSE_DIAG: J309.14 R359.2 R362.2 U307.14 U308.14 | length 290.7
  Layer 4 w0.203: J309.14@16.312,81.877 17.436,81.877 17.677,82.118 17.677,85.877 16.661,86.893 11.2,86.893 8.661,89.432 8.661,129.795 29.514,150.648 83.628,150.648 87.884,154.904 123.876,154.904 128.209,150.571 161.376,150.571 165.71,154.904 184.131,154.904 186.313,152.722 v3(202.615,152.722) 202.615,141.739 v3(201.792,140.916)
  Layer 6 w0.203: v3(201.792,140.916) R359.2@203.659,140.916 203.659,141.602 204.015,141.958 U307.14@208.144,141.958 ; v3(202.615,152.722) 203.842,152.722 R362.2@203.913,152.651 203.913,153.401 204.256,153.743 U308.14@208.119,153.743
CLLLC_VPRIM: C346.1 J313.18 R347.2 | length 18.4
  Layer 6 w0.254: R347.2@10.43,109.83 10.43,110.592 11.293,111.455 19.533,111.455 20.117,110.871 20.117,108.12 19.71,107.713 18.812,107.713 C346.1@18.373,107.274 ; J313.18@16.312,106.108 16.877,106.108 17.855,107.086 C346.1@18.373,107.086
CLLLC_VSEC: C332.1 J313.16 R323.2 | length 3.2
  Layer 6 w0.254: J313.16@16.312,104.838 C332.1@18.373,104.838 R323.2@18.373,105.943
DCLINK: C319.2 C320.2 C387.1 C388.1 C389.1 C390.1 C391.1 C392.1 C393.1 C394.1 C395.1 C396.1 J305.1 R355.1 TP308.1 TP310.1 TP320.1 TP322.1
  other v1: 46.161,59.992 44.612,60.601 47.914,60.601 44.002,62.075 48.512,62.227 44.586,63.776 47.939,63.853 46.169,64.488 46.278,68.646 46.278,70.374 39.293,70.688 40.41,70.688 41.579,70.688 39.293,71.811 40.41,71.811 41.579,71.811 46.278,72.102 39.293,72.934 40.41,72.934 41.579,72.934 46.278,73.83 39.293,74.056 40.41,74.056 41.579,74.056 39.293,75.179 40.41,75.179 41.579,75.179 46.278,75.558 39.293,76.302 40.41,76.302 41.579,76.302 46.278,77.286 39.293,77.424 40.41,77.424 41.579,77.424 39.293,78.547 40.41,78.547 41.579,78.547 46.278,78.915 39.293,79.67 40.41,79.67 41.579,79.67 46.278,80.643 39.293,80.792 40.41,80.792 41.579,80.792 39.293,81.915 40.41,81.915 41.579,81.915 46.278,82.371 39.293,83.038 40.41,83.038 41.579,83.038 46.278,84.099 39.293,84.16 40.41,84.16 41.579,84.16 39.293,85.283 40.41,85.283 41.579,85.283 46.278,85.827 39.293,86.406 40.41,86.406 41.579,86.406 39.293,87.528 40.41,87.528 41.579,87.528 46.278,87.653 46.278,89.381 46.278,91.109 46.278,92.837 46.228,96.774 44.679,97.384 47.981,97.384 44.069,98.857 48.579,99.009 44.653,100.559 48.006,100.635 46.236,101.27 46.125,105.791 46.125,107.484 46.125,109.178 46.125,110.871
IPRI_SENSE: J306.1 R300.1 R302.1 R304.1 R306.1 R309.1 R348.2 | length 10.3
  Layer 1 w0.2: R304.1@27.143,49.938 28.271,49.938 28.606,50.273 28.606,56.229 27.38,57.455 R348.2@27.38,58.43
  other v1: 21.513,45.999 22.732,45.999 23.951,45.999 25.196,45.999 21.513,47.19 22.732,47.19 23.951,47.19 25.196,47.19 21.513,48.38 22.732,48.38 23.951,48.38 25.196,48.38 21.513,49.57 22.732,49.57 23.951,49.57 25.196,49.57 21.513,50.76 22.732,50.76 23.951,50.76 25.196,50.76 21.513,51.95 22.732,51.95 23.951,51.95 25.196,51.95 21.513,53.14 22.732,53.14 23.951,53.14 25.196,53.14 21.513,54.331 22.732,54.331 23.951,54.331 25.196,54.331
ISNS_OUTN: R343.1 U307.10 | length 16.7
  Layer 6 w0.203: R343.1@191.808,137.03 192.706,137.03 193.105,137.43 205.965,137.43 206.517,136.878 U307.10@208.144,136.878
ISNS_OUTP: R337.1 U307.11 | length 16.7
  Layer 6 w0.203: R337.1@191.808,138.427 192.623,138.427 193.156,137.894 206.135,137.894 206.39,138.148 U307.11@208.144,138.148
NetC321_1: C321.1 C352.1 U307.5 | length 6.6
  Layer 6 w0.5: U307.5@217.894,139.418 219.725,139.418 220.022,139.121 C352.1@221.934,139.121 ; C352.1@221.934,138.861 224.25,138.861 C321.1@224.347,138.959
NetC321_2: C321.2 C352.2 C356.1 C358.2 C359.2 FB300.2 U307.2 U307.8 | length 26.5
  Layer 6 w0.305: C356.1@224.017,143.088 C356.1@224.068,143.037
  Layer 6 w0.5: C356.1@224.017,143.088 224.004,143.101 C358.2@220.436,143.101 219.267,143.101 219.14,143.228 U307.2@217.894,143.228 216.531,143.228 216.229,142.926 216.229,136.017 216.638,135.608 U307.8@217.894,135.608 219.648,135.608 220.002,135.961 C352.2@221.934,135.961 222.337,135.559 C321.2@224.347,135.559 225.211,134.695 FB300.2@225.211,132.984
NetC324_1: C324.1 C326.1 C369.1 C370.1 C371.1 C372.1 C373.1 C374.1 C375.1 C376.1 C387.2 C388.2 C389.2 C390.2 C391.2 C392.2 C393.2 C394.2 C395.2 C396.2
  other v1: 51.383,68.659 51.383,70.387 51.383,72.115 51.383,73.843 51.383,75.571 51.383,77.299 51.383,78.928 51.383,80.656 51.383,82.384 51.383,84.112 51.383,85.84 51.383,87.666 51.383,89.394 51.383,91.122 51.383,106.773 51.383,108.466 51.383,110.16
NetC327_1: C327.1 C329.1 R311.2 R312.2 R316.1 U301.3 | length 7.9
  Layer 6 w0.254: R312.2@120.681,144.996 120.681,146.253 C329.1@120.544,146.39 120.746,146.592 R316.1@120.746,147.614 120.817,147.685 U301.3@120.817,149.367 121.907,149.367 122.304,148.97 C327.1@122.789,148.97 R311.2@124.059,148.97
NetC329_2: C329.2 R314.2 R315.1 | length 3
  Layer 6 w0.254: R314.2@117.963,145.007 117.963,146.522 R315.1@117.986,146.544 118.14,146.39 C329.2@119.344,146.39
NetC331_1: C331.1 R313.1 R317.2 U301.1 | length 155.9
  Layer 4 w0.254: v3(10.591,104.826) 10.591,110.338 13.283,113.03 23.038,113.03 24.054,114.046 24.054,139.217 35.001,150.165 83.823,150.165 88.011,154.353 v3(122.402,154.353)
  Layer 6 w0.254: v3(10.591,104.826) 11.68,104.826 R313.1@11.693,104.838 ; U301.1@120.817,151.267 121.103,151.553 C331.1@121.103,153.126 R317.2@121.103,154.371
  Layer 6 w0.5: R317.2@121.103,154.371 121.121,154.353 v3(122.402,154.353)
NetC331_2: C331.2 R315.2 R317.1 U301.4 | length 8
  Layer 6 w0.254: R315.2@117.986,147.745 117.986,149.136 U301.4@118.217,149.367 119.163,149.367 119.455,149.66 119.455,151.727 119.903,152.175 C331.2@119.903,153.126 R317.1@119.903,154.371
NetC334_2: C334.2 R318.2 R321.2 U303.3 | length 5.5
  Layer 6 w0.203: R318.2@185.105,154 185.105,152.772 C334.2@185.121,152.756 184.744,152.379 U303.3@184.744,150.905 185.832,150.905 R321.2@186.623,150.114
NetC335_1: C335.1 C337.1 R319.2 R322.2 R329.1 U302.3 | length 8.3
  Layer 6 w0.254: R322.2@88.838,144.078 88.829,144.087 C337.1@88.829,145.535 88.829,146.608 R329.1@89,146.78 89,148.416 U302.3@88.945,148.471 90.335,148.471 90.64,148.166 C335.1@91.277,148.166 91.282,148.161 R319.2@92.623,148.161
NetC336_1: C336.1 R320.2 R321.1 | length 2.9
  Layer 6 w0.203: R321.1@187.823,150.114 189.05,150.114 C336.1@189.186,149.978 189.272,150.063 R320.2@190.585,150.063
NetC336_2: C336.2 R325.2 R326.1 | length 2.9
  Layer 6 w0.203: R326.1@187.788,148.768 189.177,148.768 C336.2@189.186,148.778 189.247,148.717 R325.2@190.62,148.717
NetC337_2: C337.2 R327.2 R328.1 | length 2.9
  Layer 6 w0.254: R327.2@86.281,144.106 86.281,145.603 86.349,145.535 C337.2@87.629,145.535
NetC340_1: C340.1 R324.1 R330.2 U302.1 | length 110.5
  Layer 4 w0.254: v3(20.37,102.311) 27.889,109.831 27.889,137.084 37.033,146.228 86.054,146.228 v3(90.093,150.266)
  Layer 6 w0.254: R324.1@19.547,102.311 v3(20.37,102.311) ; C340.1@89.032,153.257 89.032,152.032 R330.2@89.06,152.005 89.06,150.487 U302.1@88.945,150.371 89.988,150.371 v3(90.093,150.266)
NetC340_2: C340.2 R328.2 R330.1 U302.4 | length 7.6
  Layer 6 w0.254: R328.2@86.298,146.821 86.298,148.425 U302.4@86.345,148.471 87.228,148.471 87.86,149.104 R330.1@87.86,152.005 87.86,153.229 C340.2@87.832,153.257
NetC341_1: C341.1 R323.1 R331.1 U303.1 | length 199.3
  Layer 4 w0.254: v3(20.548,105.969) 27.127,112.548 27.127,137.462 36.579,146.914 85.664,146.914 89.738,150.988 95.961,150.987 96.714,150.987 100.051,147.65 164.87,147.65 168.199,150.979 v3@178.79,150.978
  Layer 6 w0.254: R323.1@19.573,105.943 19.598,105.969 v3(20.548,105.969) ; v3(178.79,150.952) 179.629,150.952 R331.1@179.67,150.994 C341.1@180.915,150.994 182.755,150.994 U303.1@182.844,150.905
NetC341_2: C341.2 R326.2 R331.2 U303.4 | length 8.4
  Layer 6 w0.203: R331.2@179.67,149.794 C341.2@180.915,149.794 184.114,149.794 184.744,149.164 U303.4@184.744,148.155 185.975,148.155 R326.2@186.588,148.768
NetC343_2: C343.2 R334.2 R338.2 U304.3 | length 5.5
  Layer 6 w0.203: R334.2@185.874,140.935 184.63,140.935 C343.2@184.604,140.91 184.604,139.284 U304.3@184.488,139.167 185.228,139.167 185.917,138.478 R338.2@186.621,138.478
NetC345_1: C345.1 R339.1 R350.2 U306.3 | length 5.3
  Layer 6 w0.254: U306.3@4.848,109.84 4.867,109.859 4.867,111.227 4.867,112.627 4.966,112.725 6.932,112.725 R350.2@7.188,112.469
NetC347_1: C347.1 R337.2 R338.1 | length 2.9
  Layer 6 w0.203: R338.1@187.821,138.478 187.957,138.341 C347.1@189.202,138.341 189.288,138.427 R337.2@190.608,138.427
NetC347_2: C347.2 R343.2 R344.1 | length 2.8
  Layer 6 w0.203: R344.1@187.846,137.055 187.932,137.141 C347.2@189.202,137.141 189.313,137.03 R343.2@190.608,137.03
NetC351_1: C351.1 R341.1 R354.2 U304.1 | length 213.5
  Layer 4 w0.203: v3(18.668,109.83) 23.495,109.83 26.34,112.674 26.34,137.77 36.17,147.599 85.452,147.599 89.535,151.683 96.85,151.683 100.273,148.26 164.192,148.26 167.615,151.683 179.149,151.683 182.625,148.207 v3(182.625,140.31)
  Layer 6 w0.203: R341.1@17.668,109.83 v3(18.668,109.83) ; R354.2@179.397,139.179 C351.1@180.642,139.179 182.575,139.179 U304.1@182.588,139.167 182.588,140.272 v3(182.625,140.31)
NetC351_2: C351.2 R344.2 R354.1 U304.4 | length 8.7
  Layer 6 w0.203: R354.1@179.397,137.979 C351.2@180.642,137.979 183.926,137.979 184.488,137.418 U304.4@184.488,136.417 185.203,136.417 185.841,137.055 R344.2@186.646,137.055
NetC353_1: C353.1 R357.2 U307.7 | length 10.6
  Layer 6 w0.305: U307.7@217.894,136.878 219.944,136.878 C353.1@219.979,136.913 220.572,136.913 220.842,137.183 226.354,137.183 226.684,136.852 R357.2@226.684,135.319
NetC353_2: C353.2 R358.2 U307.6 | length 12.1
  Layer 6 w0.305: U307.6@217.894,138.148 220.499,138.148 220.906,137.741 227.014,137.741 227.98,136.776 R358.2@227.98,135.303
NetC356_2: C356.2 C358.1 C359.1 U307.1 U307.3 | length 17.4
  Layer 6 w0.305: C359.1@222.354,144.625 C359.1@222.417,144.688
  Layer 6 w0.5: U307.3@217.894,141.958 221.086,141.958 221.607,141.437 C356.2@224.068,141.437 224.799,141.437 225.145,141.783 225.145,143.942 224.398,144.688 C359.1@222.417,144.688 ; U307.1@217.894,144.498 219.394,144.498 219.521,144.625 C358.1@220.436,144.625 C359.1@222.354,144.625
NetC357_1: C357.1 U307.13 U307.16 | length 9.6
  Layer 6 w0.5: C357.1@205.271,144.892 206.503,144.892 206.898,144.498 U307.16@208.144,144.498 209.374,144.498 209.676,144.196 209.676,140.855 209.509,140.688 U307.13@208.144,140.688
NetC360_1: C360.1 C361.1 U308.5 | length 6.6
  Layer 6 w0.5: U308.5@217.869,151.203 224.146,151.203 C360.1@224.347,151.405
NetC360_2: C360.2 C361.2 C365.1 C367.2 C368.2 FB303.2 U308.2 U308.8 | length 26.5
  Layer 6 w0.305: C360.2@224.347,148.005 225.438,148.005 225.744,147.698 FB303.2@225.744,145.837
  Layer 6 w0.5: C365.1@223.662,155.001 223.547,154.886 C367.2@220.334,154.886 219.293,154.886 219.166,155.013 U308.2@217.869,155.013 216.709,155.013 216.356,154.661 216.356,147.599 216.562,147.393 U308.8@217.869,147.393 220.004,147.393 220.815,148.204 C361.2@221.909,148.204 222.108,148.005 C360.2@224.347,148.005
NetC362_1: C362.1 R360.2 U308.7 | length 10.4
  Layer 6 w0.305: U308.7@217.869,148.663 219.013,148.663 219.252,148.902 C362.1@219.928,148.902 220.484,148.902 220.829,149.248 226.887,149.248 227.141,148.994 R360.2@227.141,148.226
NetC362_2: C362.2 R361.2 U308.6 | length 12.1
  Layer 6 w0.305: U308.6@217.869,149.933 218.988,149.933 219.156,150.102 C362.2@219.928,150.102 220.483,150.102 220.677,149.908 227.802,149.908 228.538,149.171 R361.2@228.538,148.197
NetC365_2: C365.2 C367.1 C368.1 U308.1 U308.3 | length 17.3
  Layer 6 w0.5: U308.3@217.869,153.743 220.817,153.743 221.16,153.401 C365.2@223.662,153.401 224.749,153.401 225.145,153.796 225.145,155.931 224.652,156.423 C368.1@221.934,156.423 220.347,156.423 C367.1@220.334,156.41 219.369,156.41 219.242,156.283 U308.1@217.869,156.283
NetC366_1: C366.1 U308.13 U308.16 | length 9.4
  Layer 6 w0.5: C366.1@205.475,156.702 206.618,156.702 207.037,156.283 U308.16@208.119,156.283 209.272,156.283 209.676,155.88 209.676,152.677 209.473,152.473 U308.13@208.119,152.473
NetC377_1: C377.1 C378.1 C379.1 C380.1 C381.1 C382.1 C383.1 C384.1 C385.1 C386.1 C397.2 C398.2 C399.2 C400.2 C401.2 C402.2 C403.2 C404.2 C405.2 C406.2
  other v1: 198.195,50.399 197.078,51.511 195.985,52.629 194.893,53.696 193.75,54.864 192.658,56.007 190.601,75.377 190.601,76.855 190.601,78.334 190.601,79.812 190.601,81.29 190.601,82.768 190.601,84.247 190.601,85.725 188.797,105.867 187.705,106.985 186.613,108.052 185.47,109.22 184.378,110.363
NetFB301_2: FB301.2 R357.1 | length 1.2
  Layer 6 w0.203: FB301.2@226.633,132.984 226.684,133.035 R357.1@226.684,134.119
NetFB302_2: FB302.2 R358.1 | length 1.1
  Layer 6 w0.203: R358.1@227.98,134.103 227.98,133.035 FB302.2@228.03,132.984
NetFB304_2: FB304.2 R360.1 | length 1.2
  Layer 6 w0.305: R360.1@227.141,147.026 227.167,147.001 FB304.2@227.167,145.837
NetFB305_2: FB305.2 R361.1 | length 1.1
  Layer 6 w0.305: FB305.2@228.538,145.862 R361.1@228.538,146.997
